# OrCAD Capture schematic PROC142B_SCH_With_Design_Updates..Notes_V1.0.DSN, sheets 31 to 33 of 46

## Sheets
31 31. JTAG BUFFER: size C; title: SOC JTAG INTERFACE AND JTAG BUFFERS
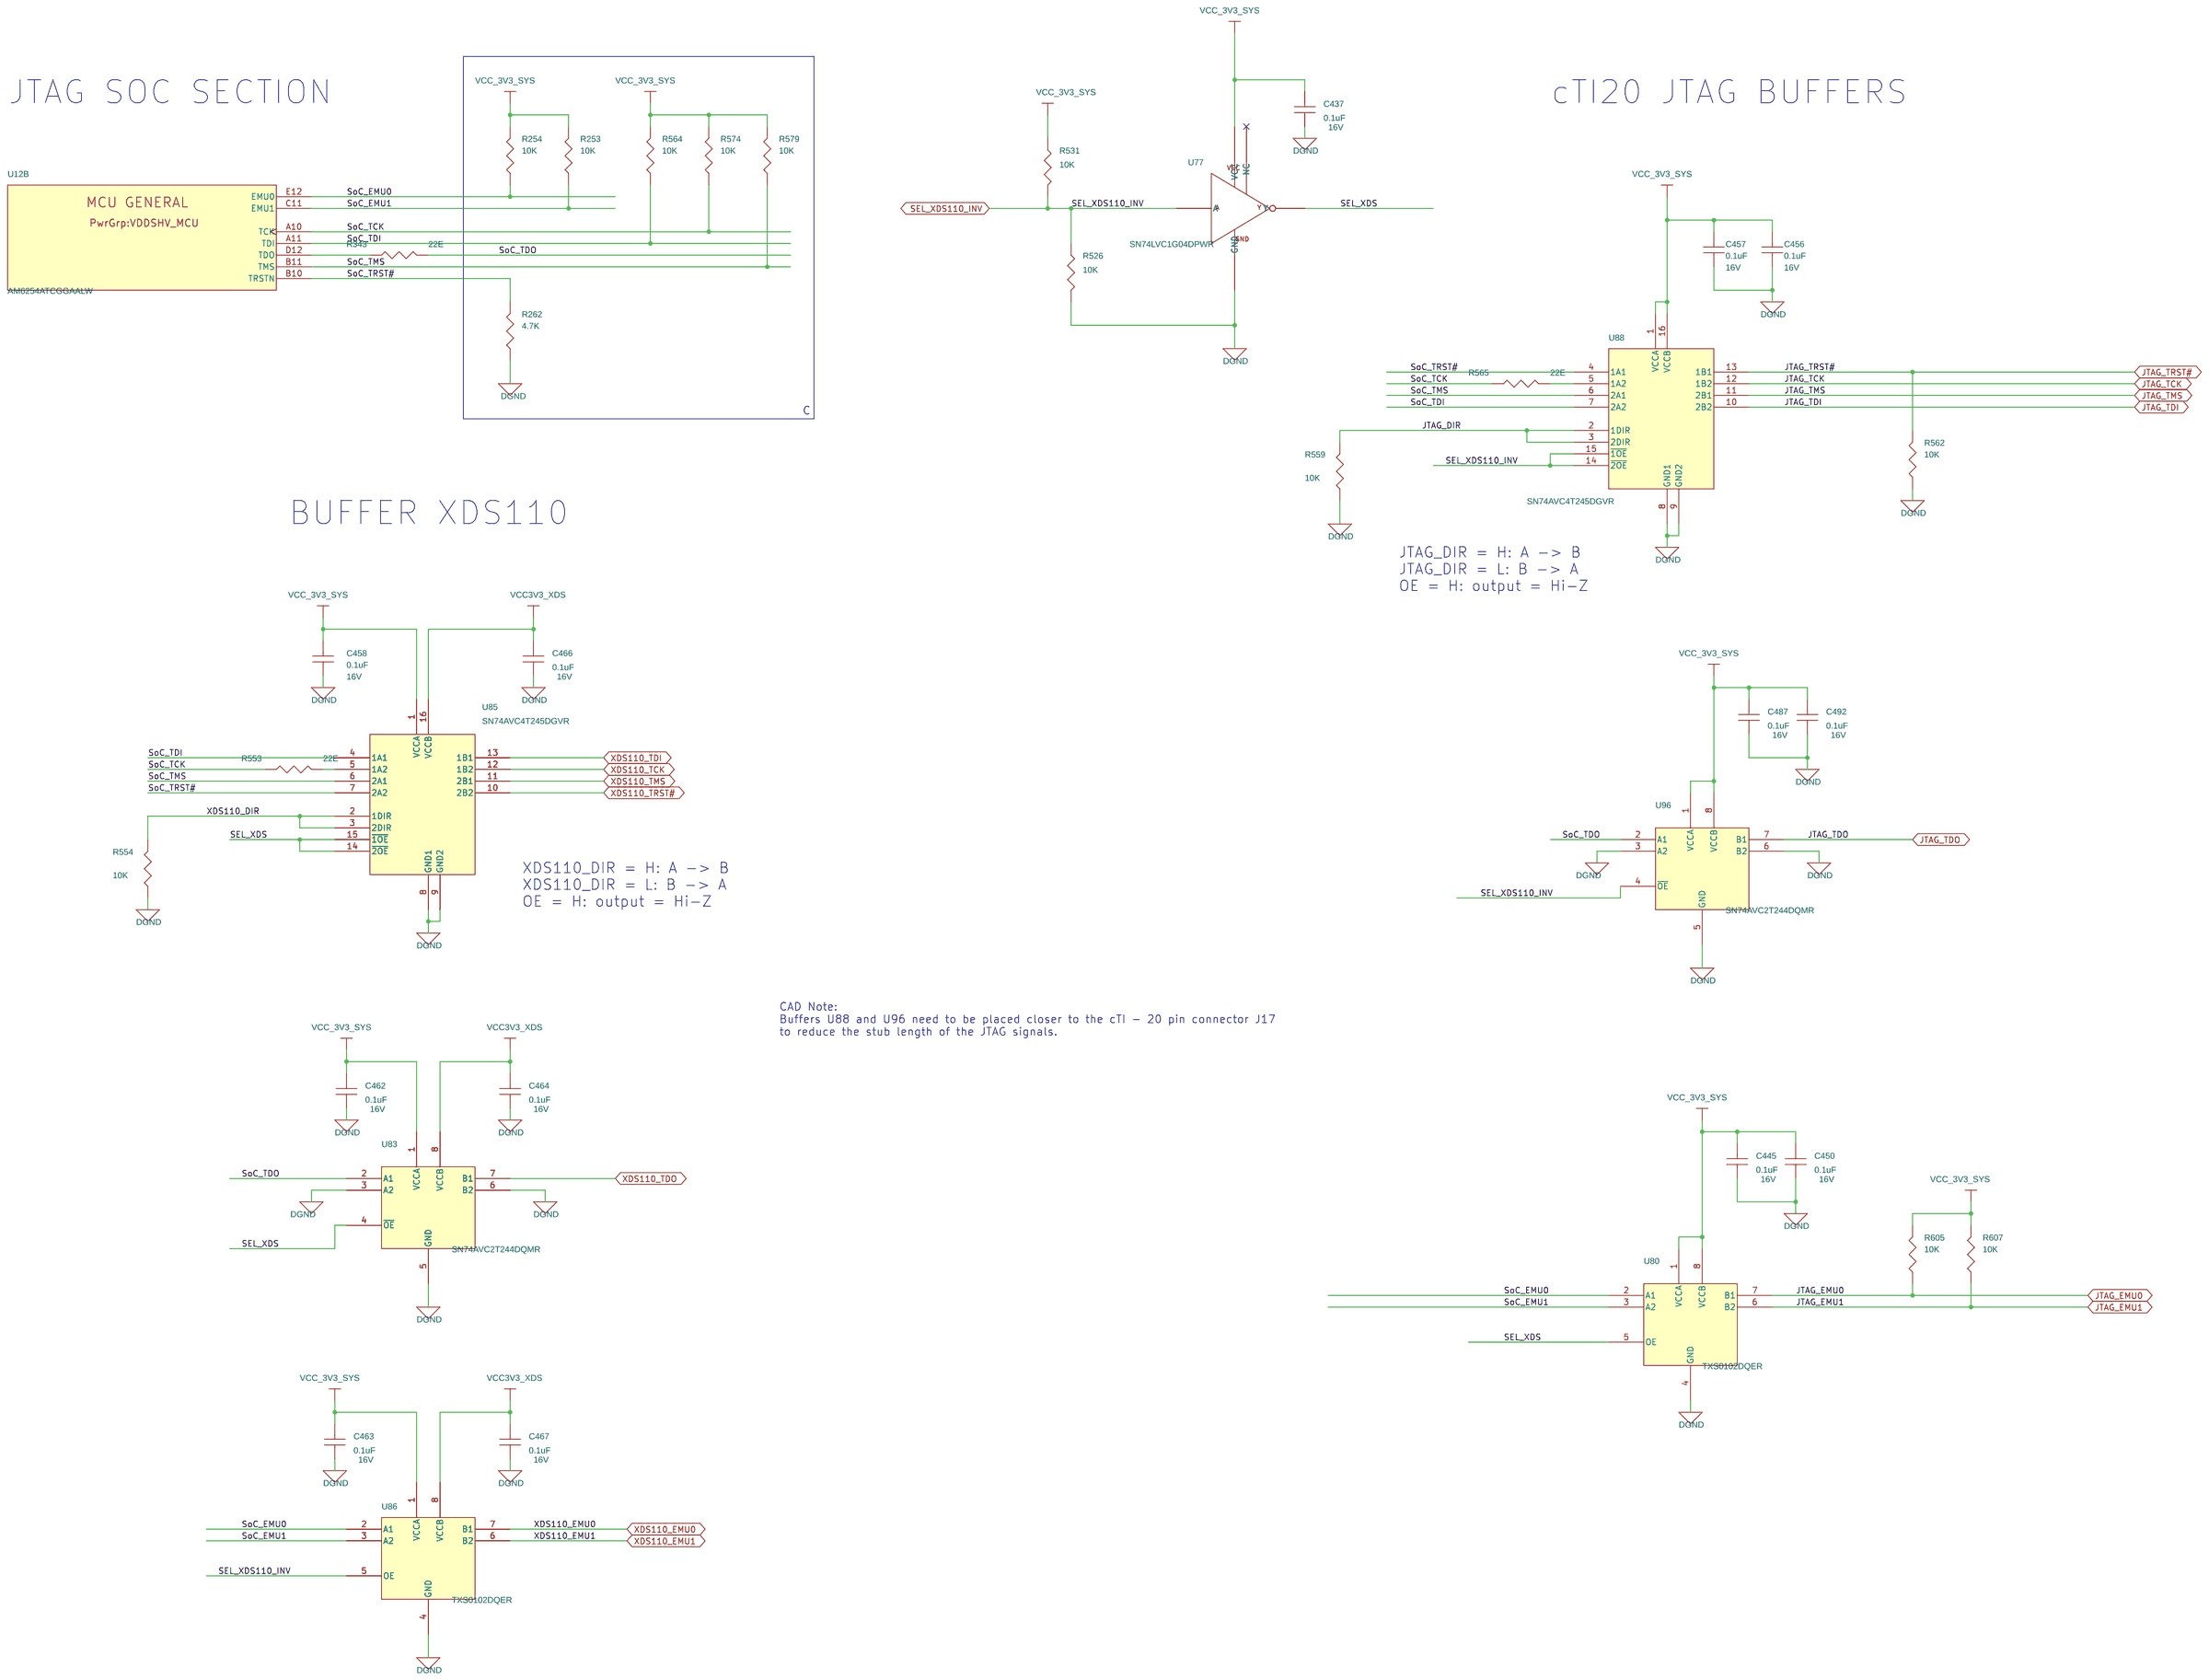
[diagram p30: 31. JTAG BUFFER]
32 32. JTAG 20 PIN cTI CONNECTOR: size C; title: JTAG 20 PIN cTI CONNECTOR AND BUFFERS
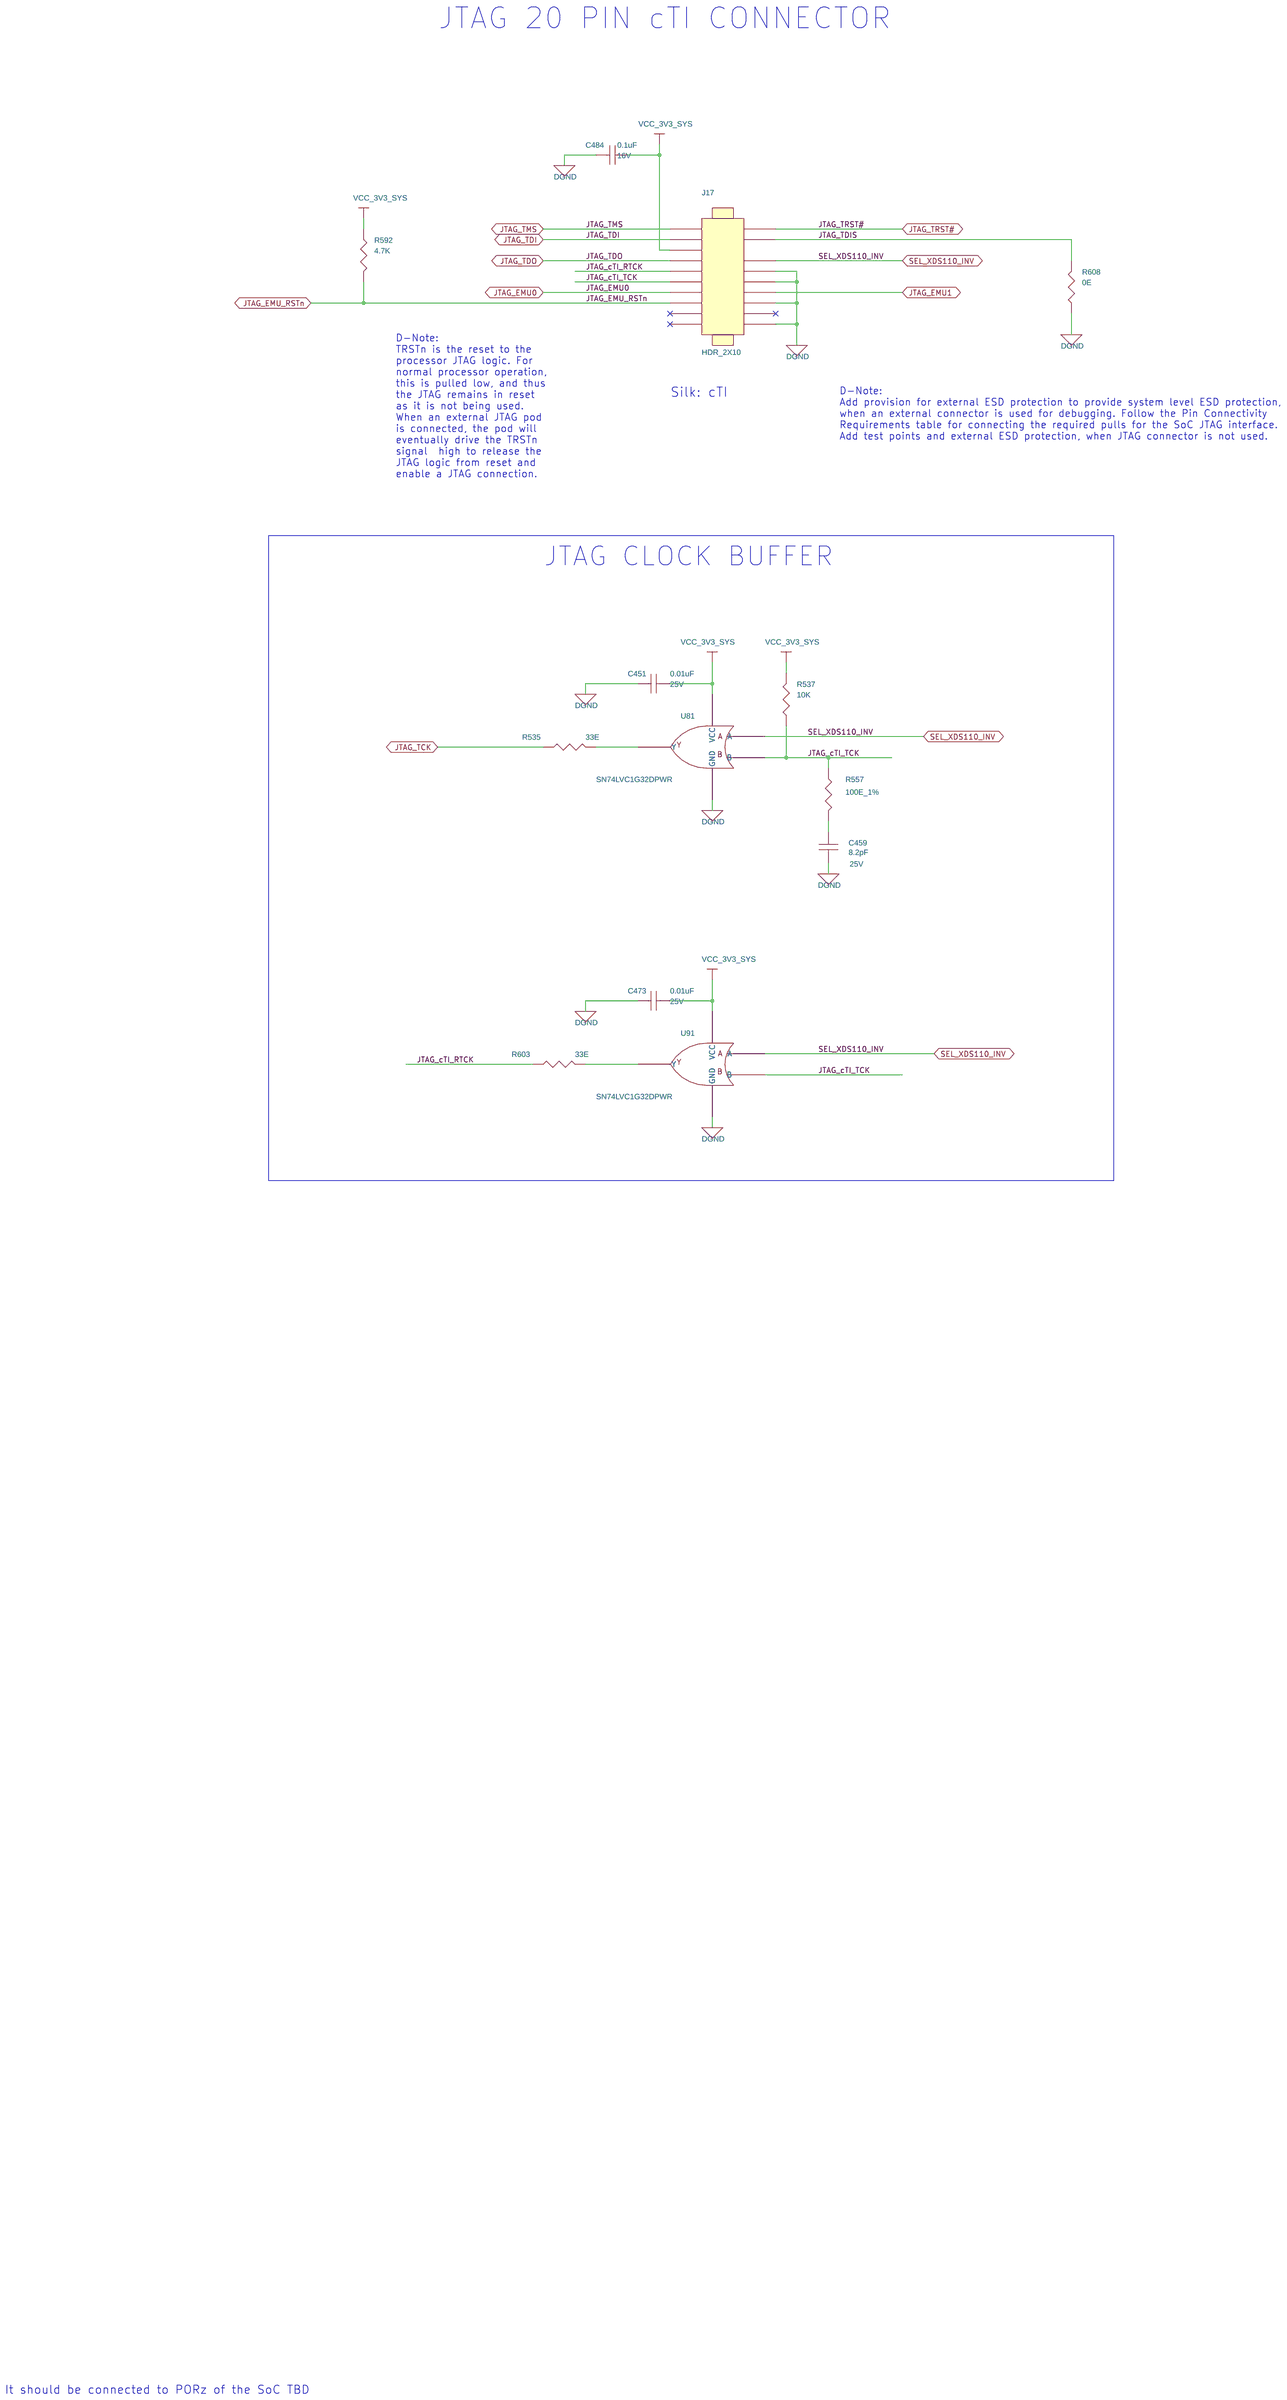
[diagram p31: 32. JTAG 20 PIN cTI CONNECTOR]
33 33. FT4232 UART TO USB BRIDGE: size C; title: FT4232 UART TO USB BRIDGE
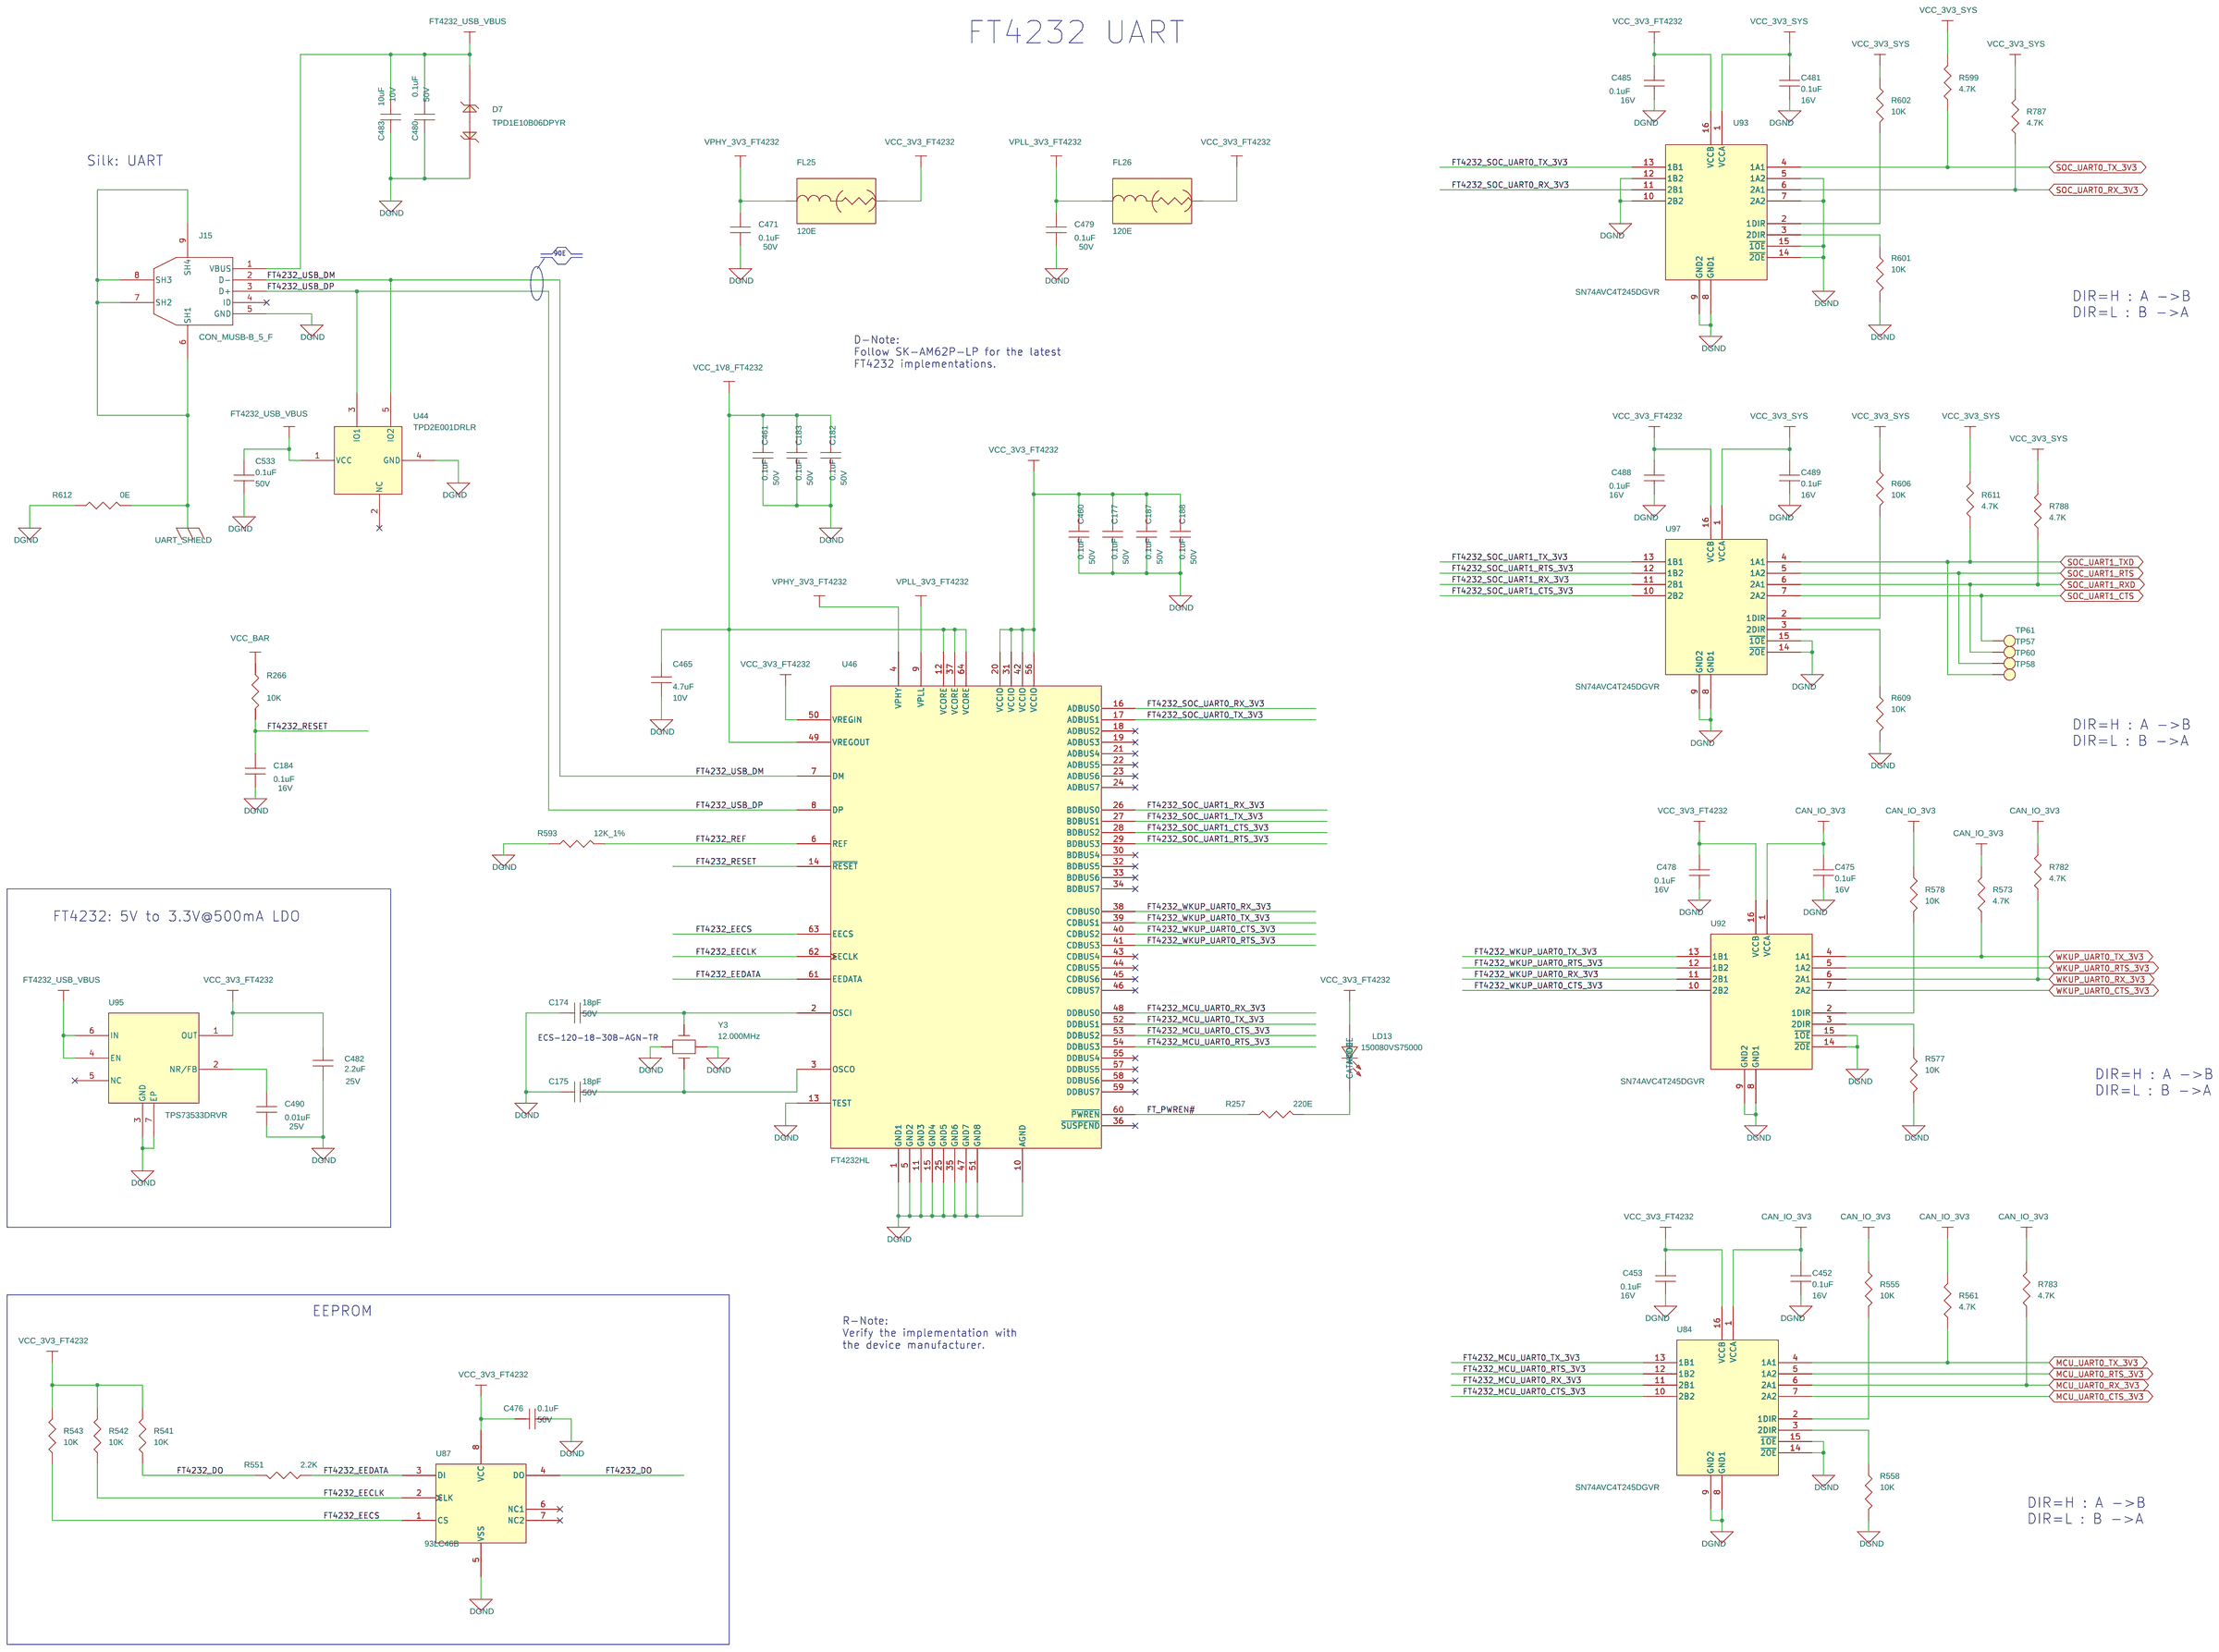
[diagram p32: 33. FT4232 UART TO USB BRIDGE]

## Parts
sheet 31. JTAG BUFFER
C437  0.1uF  [CAP0201_0-5]
C445  0.1uF  [CAP0201_0-5]
C450  0.1uF  [CAP0201_0-5]
C456  0.1uF  [CAP0201_0-5]
C457  0.1uF  [CAP0201_0-5]
C458  0.1uF  [CAP0201_0-5]
C462  0.1uF  [CAP0201_0-5]
C463  0.1uF  [CAP0201_0-5]
C464  0.1uF  [CAP0201_0-5]
C466  0.1uF  [CAP0201_0-5]
C467  0.1uF  [CAP0201_0-5]
C487  0.1uF  [CAP0201_0-5]
C492  0.1uF  [CAP0201_0-5]
R253  10K  [RES0201_0-5]
R254  10K  [RES0201_0-5]
R262  4.7K  [RES0201_0-5]
R343  22E  [RES0402_0-5]
R526  10K  [RES0201_0-5]
R531  10K  [RES0201_0-5]
R553  22E  [RES0402_0-5]
R554  10K  [RES0201_0-5]
R559  10K  [RES0201_0-5]
R562  10K  [RES0201_0-5]
R564  10K  [RES0201_0-5]
R565  22E  [RES0402_0-5]
R574  10K  [RES0201_0-5]
R579  10K  [RES0201_0-5]
R605  10K  [RES0201_0-5]
R607  10K  [RES0201_0-5]
U77  SN74LVC1G04DPWR  [X2SON5_TLV7021_30X30_0-4]
U80  TXS0102DQER  [X2SON8_TXS0102_40X60_0-4]
U83  SN74AVC2T244DQMR  [X2SON8_15-74_70X50]
U85  SN74AVC4T245DGVR  [TVSOP16_15-74_150X180]
U86  TXS0102DQER  [X2SON8_TXS0102_40X60_0-4]
U88  SN74AVC4T245DGVR  [TVSOP16_15-74_150X180]
U96  SN74AVC2T244DQMR  [X2SON8_15-74_70X50]
sheet 32. JTAG 20 PIN cTI CONNECTOR
C451  0.01uF  [CAP0201_0-5]
C459  8.2pF  [CAP0201_0-5]
C473  0.01uF  [CAP0201_0-5]
C484  0.1uF  [CAP0201_0-5]
J17  HDR_2X10  [HDR_2X10_FTR-110-51-D-06_S_S_8-7]
R535  33E  [RES0201_0-5]
R537  10K  [RES0201_0-5]
R557  100E_1%  [RES0402_0-5]
R592  4.7K  [RES0201_0-5]
R603  33E  [RES0201_0-5]
R608  0E  [RES0201_0-5]
U81  SN74LVC1G32DPWR  [X2SON5_TLV7021_30X30_0-4]
U91  SN74LVC1G32DPWR  [X2SON5_TLV7021_30X30_0-4]
sheet 33. FT4232 UART TO USB BRIDGE
C174  18pF  [CAP0402_0-75]
C175  18pF  [CAP0402_0-75]
C177  0.1uF  [CAP0402_0-75]
C182  0.1uF  [CAP0402_0-75]
C183  0.1uF  [CAP0402_0-75]
C184  0.1uF  [CAP0201_0-5]
C187  0.1uF  [CAP0402_0-75]
C188  0.1uF  [CAP0402_0-75]
C452  0.1uF  [CAP0201_0-5]
C453  0.1uF  [CAP0201_0-5]
C460  0.1uF  [CAP0402_0-75]
C461  0.1uF  [CAP0402_0-75]
C465  4.7uF  [CAP0402_0-75]
C471  0.1uF  [CAP0402_0-75]
C475  0.1uF  [CAP0201_0-5]
C476  0.1uF  [CAP0402_0-75]
C478  0.1uF  [CAP0201_0-5]
C479  0.1uF  [CAP0402_0-75]
C480  0.1uF  [CAP0402_0-75]
C481  0.1uF  [CAP0201_0-5]
C482  2.2uF  [CAP0402_0-75]
C483  10uF  [CAP0402_0-75]
C485  0.1uF  [CAP0201_0-5]
C488  0.1uF  [CAP0201_0-5]
C489  0.1uF  [CAP0201_0-5]
C490  0.01uF  [CAP0201_0-5]
C533  0.1uF  [CAP0402_0-75]
D7  TPD1E10B06DPYR  [DIO_DFN0402_0-5]
FL25  120E  [EMIFIL_BLM15A_0402_0-6]
FL26  120E  [EMIFIL_BLM15A_0402_0-6]
J15  CON_MUSB-B_5_F  [CON_MUSBB5_629105150521_S_R_S_2-7]
LD13  150080VS75000  [LED_150080VS75000_80X50_SMD_0-8]
R257  220E  [RES0402_0-5]
R266  10K  [RES0402_0-5]
R541  10K  [RES0201_0-5]
R542  10K  [RES0201_0-5]
R543  10K  [RES0201_0-5]
R551  2.2K  [RES0402_0-5]
R555  10K  [RES0201_0-5]
R558  10K  [RES0201_0-5]
R561  4.7K  [RES0201_0-5]
R573  4.7K  [RES0201_0-5]
R577  10K  [RES0201_0-5]
R578  10K  [RES0201_0-5]
R593  12K_1%  [RES0402_0-5]
R599  4.7K  [RES0201_0-5]
R601  10K  [RES0201_0-5]
R602  10K  [RES0201_0-5]
R606  10K  [RES0201_0-5]
R609  10K  [RES0201_0-5]
R611  4.7K  [RES0201_0-5]
R612  0E  [RES0805_0-75]
R782  4.7K  [RES0201_0-5]
R783  4.7K  [RES0201_0-5]
R787  4.7K  [RES0201_0-5]
R788  4.7K  [RES0201_0-5]
TP57  THRU HOLE  [TP_36X22]
TP58  THRU HOLE  [TP_36X22]
TP60  TP20_SMD  [TP20_SMD]
TP61  TP20_SMD  [TP20_SMD]
U44  TPD2E001DRLR  [SOT553-5_0-6]
U46  FT4232HL  [LQFP64_19-68_390X390_1-6]
U84  SN74AVC4T245DGVR  [TVSOP16_15-74_150X180]
U87  93LC46B  [MSOP8_25-59_125X125_1-1]
U92  SN74AVC4T245DGVR  [TVSOP16_15-74_150X180]
U93  SN74AVC4T245DGVR  [TVSOP16_15-74_150X180]
U95  TPS73533DRVR  [SON6_25-59_85X85]
U97  SN74AVC4T245DGVR  [TVSOP16_15-74_150X180]
Y3  12.000MHz  [XTAL4_ECX-53BQ_200X130_SMD_0-9]
sheet 43. HDMI INTERFACE
U12  AM6254ATCGGAALW  [BGA425_19-68_510X510_0-7]  (sections A,B,C,D,E,F,G,H,I,J,K,L,M,N,O,P,Q,R)

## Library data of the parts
C184 C437 C445 C450 C452 C453 C456-C458 C462-C464 C466 C467 C475 C478 C481 C484 C485 C487-C489 C492 = CAP: CAP CERAMIC 0.1uF 16V 10% X5R 0201; Alt_Mfr_name: YAGEO AMERICA; Alt_Mfr_part_number: CC0402KRX5R8BB104; Chkd/date: MANIRAJA/230118; Crtd /date: MANIRAJA/230118; Custom_Duty: 15%; Customs_HS_Code: 85322990; Distributor_name: DIGIKEY; Distributor_part_number: 490-14305-1-ND; Footprint Path: Y:\MIS_DATABASE\Library\ALTIUM_TOOL\PCB_FOOTPRINTS\Altium_Footprint_Lib.PcbLib; Height: 0.33MM; Library Path: Y:\MIS_DATABASE\Library\ALTIUM_TOOL\SCHEMATICS_PARTS\MS_DISCRETE_Library.schlib; Mfr_name: MURATA; Mfr_part_number: GRM033R61C104KE14D; Mistral Part No: 120009030072-R; Package: 0201; Part_type: CAPACITORS\CERAMIC; Project: TI_MAXIE_CPB; RoHS: RoHS; Temperature: -55°C+85°C; Tolerance: 10%; Voltage: 16V; Wattage: NA; Weight: 0.33mg; Datasheet: Y:\MIS_DATABASE\DATASHEETS\CAPACITORS\GRM033R61C104KE14.PDF
R253 R254 R526 R531 R537 R541-R543 R554 R555 R558 R559 R562 R564 R574 R577-R579 R601 R602 R605-R607 R609 = RESISTOR: RES 10K 1/20W 5% 0201; Chkd/date: MANIRAJA/050517; Crtd /date: MANIRAJA/050517; Custom_Duty: 15%; Customs_HS_Code: 85332119; Distributor_name: DIGIKEY; Distributor_part_number: 311-10KNCT-ND; Footprint Path: Y:\MIS_DATABASE\Library\ALTIUM_TOOL\PCB_FOOTPRINTS\Altium_Footprint_Lib.PcbLib; Height: 0.26MM; Library Path: Y:\MIS_DATABASE\Library\ALTIUM_TOOL\SCHEMATICS_PARTS\MS_DISCRETE_Library.schlib; Mfr_name: YAGEO AMERICA; Mfr_part_number: RC0201JR-0710KL; Mistral Part No: 110010070051-R; Package: 0201; Part_type: RESISTORS\FIXED; Project: GOLDEN-I LITE; RoHS: RoHS; Temperature: -55°C+125°C; Tolerance: 5%; Voltage: NA; Wattage: 1/20W; Weight: 0.17mg; Datasheet: Y:\MIS_DATABASE\DATASHEETS\RESISTORS\RCXXXXL-SER_MAR18.PDF
R262 R561 R573 R592 R599 R611 R782 R783 R787 R788 = RESISTOR: RES 4.7K 1/20W 5% 0201; Chkd/date: MANIRAJA/200921; Crtd /date: ALVY/200921; Custom_Duty: 15%; Customs_HS_Code: 85332119; Distributor_name: DIGIKEY; Distributor_part_number: 311-4.7KNCT-ND; Footprint Path: Y:\MIS_DATABASE\Library\ALTIUM_TOOL\PCB_FOOTPRINTS\Altium_Footprint_Lib.PcbLib; Height: 0.26MM; Library Path: Y:\MIS_DATABASE\Library\ALTIUM_TOOL\SCHEMATICS_PARTS\MS_DISCRETE_Library.schlib; Mfr_name: YAGEO AMERICA; Mfr_part_number: RC0201JR-074K7L; Mistral Part No: 110021090007-R; Package: 0201; Part_type: RESISTORS\FIXED; Project: TI_AM62x SKEVM_BRD; RoHS: RoHS; Temperature: -55°C+125°C; Tolerance: 5%; Voltage: NA; Wattage: 1/20W; Weight: 0.17mg; Datasheet: Y:\MIS_DATABASE\DATASHEETS\RESISTORS\RCXXXXL-SER_MAR18.PDF
R343 R553 R565 = RESISTOR: RES 22E 1/16W 5% 0402; Chkd/date: ALVY/210122; Crtd /date: TAMILARASU/210122; Custom_Duty: 15%; Customs_HS_Code: 85332119; Distributor_name: DIGIKEY; Distributor_part_number: 311-22JRCT-ND; Footprint Path: Y:\MIS_DATABASE\Library\ALTIUM_TOOL\PCB_FOOTPRINTS\Altium_Footprint_Lib.PcbLib; Height: 0.40MM; Library Path: Y:\MIS_DATABASE\Library\ALTIUM_TOOL\SCHEMATICS_PARTS\MS_DISCRETE_Library.schlib; Manufacturer: YAGEO; Mfr_name: YAGEO AMERICA; Mfr_part_number: RC0402JR-0722RL; Mistral Part No: 110022010018-R; Package: 0402; Part_type: RESISTORS\FIXED; Project: DLRL DIGITAL RECEIVER_BRD; RoHS: RoHS; Temperature: -55°C+155°C; Tolerance: 5%; Voltage: NA; Wattage: 1/16W; Weight: 0.65mg; Datasheet: Y:\MIS_DATABASE\DATASHEETS\RESISTORS\RCXXXXP-SER_SEP18.PDF
U77 = SN74LVC1G04DCKR_SC70-5: IC SINGLE INVERTER GATE X2SON5; Chkd/date: MANIRAJA/141020; Crtd /date: ALVY/131020; Custom_Duty: 15%; Customs_HS_Code: 85423100; Distributor_name: DIGIKEY; Distributor_part_number: 296-37758-1-ND; Footprint Path: Y:\MIS_DATABASE\Library\ALTIUM_TOOL\PCB_FOOTPRINTS\Altium_Footprint_Lib.PcbLib; Height: 0.40MM; Library Path: Y:\MIS_DATABASE\Library\ALTIUM_TOOL\SCHEMATICS_PARTS\MS_GATE_Library.schlib; Mfr_name: TEXAS INSTRUMENTS; Mistral Part No: 141020100010-R; Package: X2SON5; Part_type: ICS\DIGITAL\GATES; Project: AM64X_SKEVM; RoHS: RoHS; Temperature: -40°C+125°C; Tolerance: NA; Voltage: NA; Wattage: NA; Weight: 0.6mg; Datasheet: Y:\MIS_DATABASE\DATASHEETS\ICS\DIGITAL\GATES\SN74LVC1G04XX.PDF
U80 U86 = TXS0102DQX_SON8: IC 2-BIT BI-DIR VOLTAGE-LEVEL TRANSLATOR FOR OPEN-DRAIN AND PUSH-PULL X2SON8; Chkd/date: MANIRAJA/010719; Crtd /date: CHAITHANYA230512; Custom_Duty: 15%; Customs_HS_Code: 85423100; Distributor_name: DIGIKEY; Distributor_part_number: 296-28368-1-ND; Footprint Path: Y:\MIS_DATABASE\Library\ALTIUM_TOOL\PCB_FOOTPRINTS\Altium_Footprint_Lib.PcbLib; Height: 0.40MM; Library Path: Y:\MIS_DATABASE\Library\ALTIUM_TOOL\SCHEMATICS_PARTS\MS_MISCINTERFACE_Library.schlib; Mfr_name: TEXAS INSTRUMENTS; Mistral Part No: 141012050010-R; Package: X2SON8; Part_type: ICS\INTERFACE\LEVEL TRANSLATOR; Project: GEN_3-8_DB; RoHS: RoHS; Temperature: -40°C+85°C; Tolerance: NA; Voltage: NA; Wattage: NA; Weight: 1.2mg; Datasheet: Y:\MIS_DATABASE\DATASHEETS\ICS\INTERFACE\TXS0102-SER.PDF
U83 U96 = SN74AVC2T244DQMR_X2SON8: IC 2-BIT UNDIRECTIONAL VOLTAGE-LEVEL TRANSLATOR X2SON8; Chkd/date: VASANTHA/060516; Crtd /date: VASANTHA/030316; Customs_HS_Code: 15%; Distributor_name: DIGIKEY; Distributor_part_number: 296-29674-1-ND; Height: 0.40MM; Mfr_name: TEXAS INSTRUMENTS; Mistral Part No: 141016030002-R; Package: X2SON8; Part_type: ICS\INTERFACE\LEVEL TRANSLATOR; Pb-Free: 85423100; Project: OCTASIC_3600; RoHS: RoHS; Temperature: -40°C+85°C; Tolerance: NA; Voltage: NA; Wattage: NA; Weight: NA; Datasheet: Y:\MIS_DATABASE\DATASHEETS\ICS\INTERFACE\SN74AVC2T244.PDF
U84 U85 U88 U92 U93 U97 = SN74AVC4T245DGVR_TVSOP16: IC 4-BIT DUAL SUPPLY BUS TRANSCEIVER TVSOP16; Chkd/date: SUHAS/251010; Crtd /date: MAZHAR/201109; Custom_Duty: 15%; Customs_HS_Code: 85423100; Distributor_name: DIGIKEY; Distributor_part_number: 296-18054-1-ND; Height: 1.20MM; Mfr_name: TEXAS INSTRUMENTS; Mistral Part No: 141009110005-P; Package: TVSOP16; Part_type: ICS\DIGITAL\COMBINATIONAL; Project: GOLDEN-I; RoHS: Sb/ Br FREE; Temperature: -40°C+85°C; Datasheet: Y:\MIS_DATABASE\DATASHEETS\ICS\DIGITAL\BUSTRANSCEIVER\SN74AVC4T245.PDF
C451 C473 C490 = CAP: CAP CERAMIC 0.01uF 25V 10% X5R 0201; Chkd/date: MANIRAJA/230118; Crtd /date: MANIRAJA/230118; Custom_Duty: 15%; Customs_HS_Code: 85322990; Distributor_name: DIGIKEY; Distributor_part_number: GRM033R61E103KA12J-ND; Footprint Path: Y:\MIS_DATABASE\Library\ALTIUM_TOOL\PCB_FOOTPRINTS\Altium_Footprint_Lib.PcbLib; Height: 0.33MM; Library Path: Y:\MIS_DATABASE\Library\ALTIUM_TOOL\SCHEMATICS_PARTS\MS_DISCRETE_Library.schlib; Mfr_name: MURATA; Mfr_part_number: GRM033R61E103KA12J; Mistral Part No: 120018010007-R; Package: 0201; Part_type: CAPACITORS\CERAMIC; Project: TI_MAXIE_CPB; RoHS: RoHS; Temperature: -55°C+85°C; Tolerance: 10%; Voltage: 25V; Wattage: NA; Weight: 0.33mg; Datasheet: Y:\MIS_DATABASE\DATASHEETS\CAPACITORS\GRM033R61E103KA12.PDF
C459 = CAP: CAP CERAMIC 8.2pF 25V 0.5pF C0G(NP0) 0201; Chkd/date: MANIRAJA/121020; Crtd /date: ALVY/091020; Custom_Duty: 15%; Customs_HS_Code: 85322990; Distributor_name: DIGIKEY; Distributor_part_number: 490-3140-1-ND; Footprint Path: Y:\MIS_DATABASE\Library\ALTIUM_TOOL\PCB_FOOTPRINTS\Altium_Footprint_Lib.PcbLib; Height: 0.33MM; Library Path: Y:\MIS_DATABASE\Library\ALTIUM_TOOL\SCHEMATICS_PARTS\MS_DISCRETE_Library.schlib; Mfr_name: MURATA; Mfr_part_number: GRM0335C1E8R2DA01D; Mistral Part No: 120020100018-R; Package: 0201; Part_type: CAPACITORS\CERAMIC; Project: AM64X_SKEVM; RoHS: RoHS; Temperature: -55°C+125°C; Tolerance: 0.5pF%; Voltage: 25V; Wattage: NA; Weight: 0.33mg; Datasheet: Y:\MIS_DATABASE\DATASHEETS\CAPACITORS\GRM0335C1E8R2DA01.PDF
J17 = HEADER_10X2_FTR-06: CON HDR 2X10 1.27MM PITCH ST SMD; Chkd/date: MANIRAJA/031218; Crtd /date: CHAITHANYA/050811; Custom_Duty: 24%; Customs_HS_Code: 85369090; Distributor_name: DIGIKEY; Distributor_part_number: SAM8792-ND; Footprint Path: Y:\MIS_DATABASE\Library\ALTIUM_TOOL\PCB_FOOTPRINTS\Altium_Footprint_Lib.PcbLib; Height: 8.67MM; Library Path: Y:\MIS_DATABASE\Library\ALTIUM_TOOL\SCHEMATICS_PARTS\MS_CONNECTOR_Library.schlib; Mfr_name: SAMTEC; Mfr_part_number: FTR-110-51-S-D-06; Mistral Part No: 150011090001-R; Package: SMD; Part_type: CONNECTOR\HEADERS; Project: GEMYC; RoHS: RoHS; Temperature: -55°C+125°C; Tolerance: NA; Voltage: NA; Wattage: NA; Weight: NA; Datasheet: Y:\MIS_DATABASE\DATASHEETS\CONNECTORS\FTR-D-SER.PDF
R535 R603 = RESISTOR: RES 33E 1/20W 5% 0201; Chkd/date: VASANTHA/061216; Crtd /date: MAZHAR/170505; Custom_Duty: 15%; Customs_HS_Code: 85332119; Distributor_name: DIGIKEY; Distributor_part_number: P33AGCT-ND; Footprint Path: Y:\MIS_DATABASE\Library\ALTIUM_TOOL\PCB_FOOTPRINTS\Altium_Footprint_Lib.PcbLib; Height: 0.26MM; Library Path: Y:\MIS_DATABASE\Library\ALTIUM_TOOL\SCHEMATICS_PARTS\MS_DISCRETE_Library.schlib; Mfr_name: PANASONIC-ECG; Mfr_part_number: ERJ-1GEJ330C; Mistral Part No: 110010070052-R; Package: 0201; Part_type: RESISTORS\FIXED; Project: G4SLIM; RoHS: RoHS; Temperature: -55°C+125°C; Tolerance: 5%; Voltage: NA; Wattage: 1/20W; Weight: 0.15mg; Datasheet: Y:\MIS_DATABASE\DATASHEETS\RESISTORS\PAN-ERJXGE-FEB06.PDF
R557 = RESISTOR: RES 100E 1/16W 1% 0402; Chkd/date: MANIRAJA/060318; Crtd /date: NAVEED/220714; Custom_Duty: 15%; Customs_HS_Code: 85332119; Distributor_name: DIGIKEY; Distributor_part_number: 311-100LRCT-ND; Footprint Path: Y:\MIS_DATABASE\Library\ALTIUM_TOOL\PCB_FOOTPRINTS\Altium_Footprint_Lib.PcbLib; Height: 0.40MM; Library Path: Y:\MIS_DATABASE\Library\ALTIUM_TOOL\SCHEMATICS_PARTS\MS_DISCRETE_Library.schlib; Mfr_name: YAGEO AMERICA; Mfr_part_number: RC0402FR-07100RL; Mistral Part No: 110014070015-R; Package: 0402; Part_type: RESISTORS\FIXED; Project: DLRU; RoHS: RoHS; Temperature: -55°C+155°C; Tolerance: 1%; Voltage: NA; Wattage: 1/16W; Weight: 0.65mg; Datasheet: Y:\MIS_DATABASE\DATASHEETS\RESISTORS\RCXXXXL-SER_MAR18.PDF
R608 = RESISTOR: RES 0E 1/20W 5% 0201; Chkd/date: NAVEED/301214; Crtd /date: MUDDU/120710; Custom_Duty: 15%; Customs_HS_Code: 85332119; Distributor_name: DIGIKEY; Distributor_part_number: 311-0.0NCT-ND; Footprint Path: Y:\MIS_DATABASE\Library\ALTIUM_TOOL\PCB_FOOTPRINTS\Altium_Footprint_Lib.PcbLib; Height: 0.26MM; Library Path: Y:\MIS_DATABASE\Library\ALTIUM_TOOL\SCHEMATICS_PARTS\MS_DISCRETE_Library.schlib; Mfr_name: YAGEO AMERICA; Mfr_part_number: RC0201JR-070RL; Mistral Part No: 110010070067-R; Package: 0201; Part_type: RESISTORS\FIXED; Project: PB_BUGBASE; RoHS: RoHS; Temperature: -55°C+125°C; Tolerance: 5%; Voltage: NA; Wattage: 1/20W; Weight: 0.17mg; Datasheet: Y:\MIS_DATABASE\DATASHEETS\RESISTORS\RCXXXXL-SER_MAR18.PDF
U81 U91 = SN74LVC1G32_X2SON5: IC SINGLE 2-INPUT POSITIVE-OR GATE X2SON5; Chkd/date: MANIRAJA/141020; Crtd /date: ALVY/131020; Custom_Duty: 15%; Customs_HS_Code: 85423100; Distributor_name: DIGIKEY; Distributor_part_number: 296-SN74LVC1G32DPWRCT-ND; Footprint Path: Y:\MIS_DATABASE\Library\ALTIUM_TOOL\PCB_FOOTPRINTS\Altium_Footprint_Lib.PcbLib; Height: 0.40MM; Library Path: Y:\MIS_DATABASE\Library\ALTIUM_TOOL\SCHEMATICS_PARTS\MS_GATE_Library.schlib; Mfr_name: TEXAS INSTRUMENTS; Mistral Part No: 141020100011-R; Package: X2SON5; Part_type: ICS\DIGITAL\GATES; Project: AM64X_SKEVM; RoHS: RoHS; Temperature: -40°C+125°C; Tolerance: NA; Voltage: NA; Wattage: NA; Weight: 0.6mg; Datasheet: Y:\MIS_DATABASE\DATASHEETS\ICS\DIGITAL\GATES\SN74LVC1G32XX.PDF
C174 C175 = CAP: CAP CERAMIC 18pF 50V 5% HI-Q C0G(NP0) 0402; Chkd/date: VASANTHA/030315; Crtd /date: NAVEED/271014; Custom_Duty: 15%; Customs_HS_Code: 85322990; Distributor_name: DIGIKEY; Distributor_part_number: 490-3119-1-ND; Footprint Path: Y:\MIS_DATABASE\Library\ALTIUM_TOOL\PCB_FOOTPRINTS\Altium_Footprint_Lib.PcbLib; Height: 0.55MM; Library Path: Y:\MIS_DATABASE\Library\ALTIUM_TOOL\SCHEMATICS_PARTS\MS_DISCRETE_Library.schlib; Mfr_name: MURATA; Mfr_part_number: GJM1555C1H180JB01D; Mistral Part No: 120014100019-R; Package: 0402; Part_type: CAPACITORS\CERAMIC; Project: DC_MIST_RDC; RoHS: RoHS; Temperature: -55°C+125°C; Tolerance: 5%; Voltage: 50V; Wattage: NA; Weight: 6mg; Datasheet: Y:\MIS_DATABASE\DATASHEETS\CAPACITORS\MURATA-GXX-SER_NOV17.PDF
C177 C182 C183 C187 C188 C460 C461 C471 C476 C479 C480 C533 = CAP: CAP CERAMIC 0.1uF 50V 10% X7R 0402; Alt_Mfr_name: YAGEO AMERICA; Alt_Mfr_part_number: CC0402KRX5R8BB104; Chkd/date: MANIRAJA/261020; Crtd /date: ALVY/211020; Custom_Duty: 15%; Customs_HS_Code: 85322990; Distributor_name: DIGIKEY; Distributor_part_number: 490-10700-1-ND; Footprint Path: Y:\MIS_DATABASE\Library\ALTIUM_TOOL\PCB_FOOTPRINTS\Altium_Footprint_Lib.PcbLib; Height: 0.55MM; Library Path: Y:\MIS_DATABASE\Library\ALTIUM_TOOL\SCHEMATICS_PARTS\MS_DISCRETE_Library.schlib; Mfr_name: MURATA; Mfr_part_number: GRM155R71H104KE14D; Mistral Part No: 120011100014-R; Package: 0402; Part_type: CAPACITORS\CERAMIC; Project: J7_CP; RoHS: RoHS; Temperature: -55°C+125°C; Tolerance: 10%; Voltage: 50V; Wattage: NA; Weight: 3.1mg; Datasheet: Y:\MIS_DATABASE\DATASHEETS\CAPACITORS\GRM155R71H104KE14.PDF
C465 = CAP: CAP CERAMIC 4.7uF 10V 20% X5R 0402; Chkd/date: MANIRAJA/110718; Crtd /date: ALVY/110718; Custom_Duty: 15%; Customs_HS_Code: 85322990; Distributor_name: DIGIKEY; Distributor_part_number: 490-14306-1-ND; Footprint Path: Y:\MIS_DATABASE\Library\ALTIUM_TOOL\PCB_FOOTPRINTS\Altium_Footprint_Lib.PcbLib; Height: 0.65MM; Library Path: Y:\MIS_DATABASE\Library\ALTIUM_TOOL\SCHEMATICS_PARTS\MS_DISCRETE_Library.schlib; Mfr_name: MURATA; Mfr_part_number: GRM155R61A475MEAAD; Mistral Part No: 120012060002-R; Package: 0402; Part_type: CAPACITORS\CERAMIC; Project: TI_J7SVB_PCIE_ADD-ON-CARD; RoHS: RoHS; Temperature: -55°C+85°C; Tolerance: 20%; Voltage: 10V; Wattage: NA; Weight: 14mg; Datasheet: Y:\MIS_DATABASE\DATASHEETS\CAPACITORS\GRM155R61A475MEAAD.PDF
C482 = CAP: CAP CERAMIC 2.2uF 25V 10% X5R 0402; Chkd/date: ALVY/010721; Crtd /date: MANIRAJA/010721; Custom_Duty: 15%; Customs_HS_Code: 85322990; Distributor_name: DIGIKEY; Distributor_part_number: 490-12703-1-ND; Footprint Path: Y:\MIS_DATABASE\Library\ALTIUM_TOOL\PCB_FOOTPRINTS\Altium_Footprint_Lib.PcbLib; Height: 0.70MM; Library Path: Y:\MIS_DATABASE\Library\ALTIUM_TOOL\SCHEMATICS_PARTS\MS_DISCRETE_Library.schlib; Mfr_name: MURATA; Mfr_part_number: GRM155R61E225KE11D; Mistral Part No: 120015120001-R; Package: 0402; Part_type: CAPACITORS\CERAMIC; Project: TI_AM263X_CC; RoHS: RoHS; Temperature: -55°C+85°C; Tolerance: 10%; Voltage: 25V; Wattage: NA; Weight: 1.5mg; Datasheet: Y:\MIS_DATABASE\DATASHEETS\CAPACITORS\GRM155R61E225KE11.PDF
C483 = CAP: CAP CERAMIC 10uF 10V 20% X5R 0402; Chkd/date: MANIRAJA/300520; Crtd /date: ALVY/260520; Custom_Duty: 15%; Customs_HS_Code: 85322990; Distributor_name: DIGIKEY; Distributor_part_number: 490-GRM155R61A106ME11DTR-ND; Footprint Path: Y:\MIS_DATABASE\Library\ALTIUM_TOOL\PCB_FOOTPRINTS\Altium_Footprint_Lib.PcbLib; Height: 0.55MM; Library Path: Y:\MIS_DATABASE\Library\ALTIUM_TOOL\SCHEMATICS_PARTS\MS_DISCRETE_Library.schlib; Mfr_name: MURATA; Mfr_part_number: GRM155R61A106ME11D; Mistral Part No: 120013110019-R; Package: 0402; Part_type: CAPACITORS\CERAMIC; Project: QCS610_NANOSOM; RoHS: RoHS; Temperature: -55°C+85°C; Tolerance: 20%; Voltage: 10V; Wattage: NA; Weight: 3.1mg; Datasheet: Y:\MIS_DATABASE\DATASHEETS\CAPACITORS\MURATA-GXX-SER_NOV17.PDF
D7 = DIODE_SOD323: DIODE 1CH ESD PROTECTION X1SON2; Chkd/date: MANIRAJA/040420; Crtd /date: VASANTHA/181114; Custom_Duty: 15%; Customs_HS_Code: 85423100; Distributor_name: DIGIKEY; Distributor_part_number: 296-30406-1-ND; Footprint Path: Y:\MIS_DATABASE\Library\ALTIUM_TOOL\PCB_FOOTPRINTS\Altium_Footprint_Lib.PcbLib; Height: 0.45MM; Library Path: Y:\MIS_DATABASE\Library\ALTIUM_TOOL\SCHEMATICS_PARTS\MS_DISCRETE_Library.schlib; Mfr_name: TEXAS INSTRUMENTS; Mistral Part No: 130014110022-R; Package: X1SON2; Part_type: DIODE; Project: GALILEO_EVM; RoHS: RoHS; Temperature: -40°C+125°C; Tolerance: NA; Voltage: NA; Wattage: NA; Weight: 1mg; Datasheet: Y:\MIS_DATABASE\DATASHEETS\ICS\INTERFACE\TPD1E10B06-SER.PDF
FL25 FL26 = EMIFILTER_IND: IND FERRITE BEAD CHIP 120E 2A 0402; Chkd/date: NAVEED/241114; Crtd /date: USMAN/170613; Custom_Duty: 24%; Customs_HS_Code: 85369090; Distributor_name: DIGIKEY; Distributor_part_number: 490-9656-1-ND; Footprint Path: Y:\MIS_DATABASE\Library\ALTIUM_TOOL\PCB_FOOTPRINTS\Altium_Footprint_Lib.PcbLib; Height: 0.55MM; Library Path: Y:\MIS_DATABASE\Library\ALTIUM_TOOL\SCHEMATICS_PARTS\MS_FILTER_Library.schlib; Mfr_name: MURATA; Mfr_part_number: BLM15PX121SN1D; Mistral Part No: 130013060022-R; Package: 0402; Part_type: INDUCTOR; Project: GEN_3-8; RoHS: RoHS; Temperature: -55°C+125°C; Tolerance: 25%; Voltage: NA; Wattage: NA; Weight: 1mg; Datasheet: Y:\MIS_DATABASE\DATASHEETS\DISCRETES\INDUCTORS\BLM15-SN1-SER.PDF
J15 = CON_USB_MINI-B: CON MICRO USB TYPE B 5POS FEMALE RT SMD; Chkd/date: MANIRAJA/150519; Crtd /date: ALVY/150519; Custom_Duty: 24%; Customs_HS_Code: 85369090; Distributor_name: DIGIKEY; Distributor_part_number: 732-5960-1-ND; Footprint Path: Y:\MIS_DATABASE\Library\ALTIUM_TOOL\PCB_FOOTPRINTS\Altium_Footprint_Lib.PcbLib; Height: 2.66MM; Library Path: Y:\MIS_DATABASE\Library\ALTIUM_TOOL\SCHEMATICS_PARTS\MS_CONNECTOR_Library.schlib; Mfr_name: WURTH ELECTRONICS; Mfr_part_number: 629105150521; Mistral Part No: 150019050015-R; Package: SMD; Part_type: CONNECTOR\USB; Project: NEXTNAV_ALT-STATION_ATE_BRD; RoHS: RoHS; Temperature: -40°C+85°C; Tolerance: NA; Voltage: NA; Wattage: NA; Weight: 360mg; Datasheet: Y:\MIS_DATABASE\DATASHEETS\CONNECTORS\629105150521.PDF
LD13 = DIODE_LED: DIODE LED BRIGHT GREEN SMD; Chkd/date: MANIRAJA/180820; Crtd /date: ALVY/180820; Custom_Duty: 24%; Customs_HS_Code: 85439000; Distributor_name: DIGIKEY; Distributor_part_number: 732-4986-1-ND; Footprint Path: Y:\MIS_DATABASE\Library\ALTIUM_TOOL\PCB_FOOTPRINTS\Altium_Footprint_Lib.PcbLib; Height: 0.80MM; Library Path: Y:\MIS_DATABASE\Library\ALTIUM_TOOL\SCHEMATICS_PARTS\MS_OPTO_Library.schlib; Mfr_name: WURTH ELECTRONICS; Mistral Part No: 130020080012-R; Package: SMD; Part_type: OPTO\LED; Project: AM64x_EVM_BRD; RoHS: RoHS; Temperature: -40°C+85°C; Tolerance: NA; Voltage: NA; Wattage: NA; Weight: 10mg; Datasheet: Y:\MIS_DATABASE\DATASHEETS\DISCRETES\LEDS\150080VS75000.PDF
R257 = RESISTOR: RES 220E 1/10W 5% 0402; Chkd/date: VASANTHA/291216; Crtd /date: GEETHA/260406; Custom_Duty: 15%; Customs_HS_Code: 85332119; Distributor_name: DIGIKEY; Distributor_part_number: P220JCT-ND; Footprint Path: Y:\MIS_DATABASE\Library\ALTIUM_TOOL\PCB_FOOTPRINTS\Altium_Footprint_Lib.PcbLib; Height: 0.40MM; Library Path: Y:\MIS_DATABASE\Library\ALTIUM_TOOL\SCHEMATICS_PARTS\MS_DISCRETE_Library.schlib; Mfr_name: PANASONIC-ECG; Mfr_part_number: ERJ-2GEJ221X; Mistral Part No: 110009030506-R; Package: 0402; Part_type: RESISTORS\FIXED; Project: RED EYE; RoHS: RoHS; Temperature: -55°C+155°C; Tolerance: 5%; Voltage: NA; Wattage: 1/10W; Weight: 0.8mg; Datasheet: Y:\MIS_DATABASE\DATASHEETS\RESISTORS\PAN-ERJSER_NOV17.PDF
R266 = RESISTOR: RES 10K 1/16W 5% 0402; Chkd/date: MANIRAJA/120219; Crtd /date: MANIRAJA/120219; Custom_Duty: 15%; Customs_HS_Code: 85332119; Distributor_name: DIGIKEY; Distributor_part_number: 541-10KJCT-ND; Footprint Path: Y:\MIS_DATABASE\Library\ALTIUM_TOOL\PCB_FOOTPRINTS\Altium_Footprint_Lib.PcbLib; Height: 0.40MM; Library Path: Y:\MIS_DATABASE\Library\ALTIUM_TOOL\SCHEMATICS_PARTS\MS_DISCRETE_Library.schlib; Mfr_name: VISHAY; Mfr_part_number: CRCW040210K0JNED; Mistral Part No: 110011060021-R; Package: 0402; Part_type: RESISTORS\FIXED; Project: NEXTNAV_ORBIT_MODULE; RoHS: RoHS; Temperature: -55°C+155°C; Tolerance: 5%; Voltage: NA; Wattage: 1/16W; Weight: 0.65mg; Datasheet: Y:\MIS_DATABASE\DATASHEETS\RESISTORS\CRCW0603.PDF
R551 = RESISTOR: RES 2.2K 1/16W 5% 0402; Chkd/date: VASANTHA/061216; Crtd /date: BAVISH/021210; Custom_Duty: 15%; Customs_HS_Code: 85332119; Distributor_name: DIGIKEY; Distributor_part_number: 311-2.2KJRCT-ND; Footprint Path: Y:\MIS_DATABASE\Library\ALTIUM_TOOL\PCB_FOOTPRINTS\Altium_Footprint_Lib.PcbLib; Height: 0.40MM; Library Path: Y:\MIS_DATABASE\Library\ALTIUM_TOOL\SCHEMATICS_PARTS\MS_DISCRETE_Library.schlib; Mfr_name: YAGEO AMERICA; Mfr_part_number: RC0402JR-072K2L; Mistral Part No: 110010120018-R; Package: 0402; Part_type: RESISTORS\FIXED; Project: TE4; RoHS: RoHS; Temperature: -55°C+155°C; Tolerance: 5%; Voltage: NA; Wattage: 1/16W; Weight: 0.65mg; Datasheet: Y:\MIS_DATABASE\DATASHEETS\RESISTORS\RCXXXXL-SER_MAR18.PDF
R593 = RESISTOR: RES 12K 1/10W 1% 0402; Chkd/date: VASANTHA/041215; Crtd /date: VASANTHA/041215; Custom_Duty: 15%; Customs_HS_Code: 85332119; Distributor_name: DIGIKEY; Distributor_part_number: P12.0KLCT-ND; Footprint Path: Y:\MIS_DATABASE\Library\ALTIUM_TOOL\PCB_FOOTPRINTS\Altium_Footprint_Lib.PcbLib; Height: 0.40MM; Library Path: Y:\MIS_DATABASE\Library\ALTIUM_TOOL\SCHEMATICS_PARTS\MS_DISCRETE_Library.schlib; Mfr_name: PANASONIC-ECG; Mfr_part_number: ERJ-2RKF1202X; Mistral Part No: 110019040053-R; Package: 0402; Part_type: RESISTORS\FIXED; Project: TI_C5545; RoHS: RoHS; Temperature: -55°C+155°C; Tolerance: 1%; Voltage: NA; Wattage: 1/10W; Weight: 0.8mg; Datasheet: Y:\MIS_DATABASE\DATASHEETS\RESISTORS\PAN-ERJSER_NOV17.PDF
R612 = RESISTOR: RES 0E 1/8W 5% 0805; Chkd/date: VASANTHA/130416; Crtd /date: JEBRAN/020316; Custom_Duty: 15%; Customs_HS_Code: 85332119; Distributor_name: DIGIKEY; Distributor_part_number: 311-0.0ARCT-ND; Footprint Path: Y:\MIS_DATABASE\Library\ALTIUM_TOOL\PCB_FOOTPRINTS\Altium_Footprint_Lib.PcbLib; Height: 0.60MM; Library Path: Y:\MIS_DATABASE\Library\ALTIUM_TOOL\SCHEMATICS_PARTS\MS_DISCRETE_Library.schlib; Mfr_name: YAGEO AMERICA; Mfr_part_number: RC0805JR-070RL; Mistral Part No: 110009030074-R; Package: 0805; Part_type: RESISTORS\FIXED; Project: ZK_BIOMETRIC; RoHS: RoHS; Temperature: -55°C+155°C; Tolerance: 5%; Voltage: NA; Wattage: 1/8W; Weight: 5.5mg; Datasheet: Y:\MIS_DATABASE\DATASHEETS\RESISTORS\RCXXXXL-SER_MAR18.PDF
TP57 TP58 = TESTPOINT: TESTPOINT 0.56MM DRILL PTH; Chkd/date: BAVISH/040311; Crtd /date: MAZHAR/110405; Distributor_name: NA; Distributor_part_number: NA; Height: NA; Mfr_name: LOCAL; Mistral Part No: 130010010008; Package: THRU-HOLE; Project: KOPIN_MODULS; Temperature: NA; Tolerance: NA; Voltage: NA; Wattage: NA; Weight: NA; Datasheet: NA
TP60 TP61 = TESTPOINT: TESTPOINT CIR 20 SMD; Chkd/date: SHREESHAIL/171006; Crtd /date: MAZHAR/171006; Custom_Duty: NA; Customs_HS_Code: NA; Distributor_name: NA; Distributor_part_number: NA; Footprint Path: Y:\MIS_DATABASE\Library\ALTIUM_TOOL\PCB_FOOTPRINTS\Altium_Footprint_Lib.PcbLib; Height: NA; Library Path: Y:\MIS_DATABASE\Library\ALTIUM_TOOL\SCHEMATICS_PARTS\MS_DISCRETE_Library.schlib; MECHANICAL 3D STEP FILE: NA; Mfr_name: LOCAL; Mistral Part No: NA; Package: SMD; Project: BT MODULE_CSRBC04; RoHS: NA; Temperature: NA; Tolerance: NA; Voltage: NA; Wattage: NA; Weight: NA; Datasheet: NA
U44 = TPD2E001DRLR_SOT-5: IC ESD-PROTECTION DIODE ARRAYS SOT-5; Chkd/date: NAVEED/150714; Crtd /date: MUDDU/250510; Custom_Duty: 15%; Customs_HS_Code: 85423100; Distributor_name: DIGIKEY; Distributor_part_number: 296-21883-1-ND; Footprint Path: Y:\MIS_DATABASE\Library\ALTIUM_TOOL\PCB_FOOTPRINTS\Altium_Footprint_Lib.PcbLib; Height: 0.60MM; Library Path: Y:\MIS_DATABASE\Library\ALTIUM_TOOL\SCHEMATICS_PARTS\MS_FILTER_Library.schlib; Mfr_name: TEXAS INSTRUMENTS; Mistral Part No: 140110060007-R; Package: SOT-5; Part_type: ICS\ANALOG\ACTIVE FILTER; Project: CENTAURUS; RoHS: RoHS; Temperature: -40°C+85°C; Tolerance: NA; Voltage: NA; Wattage: NA; Weight: 2.8mg; Datasheet: Y:\MIS_DATABASE\DATASHEETS\ICS\MISC\TPD2E001DRLR.PDF
U46 = FT4232H_LQFP64: IC HIGH SPEED QUAD USB UART LQFP64; Chkd/date: MANIRAJA/110917; Crtd /date: VIJAYALAKSHMI/120813; Custom_Duty: 15%; Customs_HS_Code: 85423100; Distributor_name: DIGIKEY; Distributor_part_number: 768-1026-1-ND; Footprint Path: Y:\MIS_DATABASE\Library\ALTIUM_TOOL\PCB_FOOTPRINTS\Altium_Footprint_Lib.PcbLib; Height: 1.60MM; Library Path: Y:\MIS_DATABASE\Library\ALTIUM_TOOL\SCHEMATICS_PARTS\MS_COMBINATIONAL_Library.schlib; Mfr_name: FTDI; Mfr_part_number: FT4232HL-REEL; Mistral Part No: 141013080006-R; Package: LQFP64; Part_type: ICS\DIGITAL\PERIPHERAL; Project: DM37XX; RoHS: RoHS; Temperature: -40°C+85°C; Tolerance: NA; Voltage: NA; Wattage: NA; Weight: 342.7mg; Datasheet: Y:\MIS_DATABASE\DATASHEETS\ICS\DIGITAL\PERIPHERAL\FT4232HX.PDF
U87 = 93LC46B_MSOP8: IC 1K MICROWIRE COMPATIBLE SERIAL EEPROM MSOP8; Chkd/date: MANIRAJA/150218; Crtd /date: ALVY/150218; Custom_Duty: 15%; Customs_HS_Code: 85423100; Distributor_name: DIGIKEY; Distributor_part_number: 93LC46B-I/MS-ND; Footprint Path: Y:\MIS_DATABASE\Library\ALTIUM_TOOL\PCB_FOOTPRINTS\Altium_Footprint_Lib.PcbLib; Height: 1.10MM; Library Path: Y:\MIS_DATABASE\Library\ALTIUM_TOOL\SCHEMATICS_PARTS\MS_MISCMEMORY_Library.schlib; Mfr_name: MICROCHIP; Mfr_part_number: 93LC46B-I/MS; Mistral Part No: 141118020002-R; Package: MSOP8; Part_type: ICS\DIGITAL\MEMORY; Project: TI_MAXIE_CPB; RoHS: RoHS; Temperature: -40°C+85°C; Tolerance: NA; Voltage: NA; Wattage: NA; Weight: 140mg; Datasheet: Y:\MIS_DATABASE\DATASHEETS\ICS\MEMORY\93LC46B.PDF
U95 = TPS73501DRVR_SON6: IC 500mA LOW DROPOUT REGULATOR SON6; Chkd/date: VASANTHA/280915; Crtd /date: NAVEED/011014; Custom_Duty: 15%; Customs_HS_Code: 85423100; Distributor_name: DIGIKEY; Distributor_part_number: TPS73533DRVR-ND; Height: 0.80MM; Mfr_name: TEXAS INSTRUMENTS; Mistral Part No: 142014100001-R; Package: SON6; Part_type: ICS\POWER\VOLTAGE REGULATOR; Project: BLUETOOTH_WATCH; RoHS: RoHS; Temperature: -40°C+125°C; Tolerance: NA; Voltage: NA; Wattage: NA; Weight: NA; Datasheet: Y:\MIS_DATABASE\DATASHEETS\ICS\POWER\TPS735.PDF
Y3 = CRY4_13: CRY 12.000MHz 18pF SMD; Chkd/date: MANIRAJA/271021; Crtd /date: ALVY/271021; Custom_Duty: 24%; Customs_HS_Code: 85439000; Distributor_name: DIGIKEY; Distributor_part_number: XC2719CT-ND; Footprint Path: Y:\MIS_DATABASE\Library\ALTIUM_TOOL\PCB_FOOTPRINTS\Altium_Footprint_Lib.PcbLib; Height: 0.85MM; Library Path: Y:\MIS_DATABASE\Library\ALTIUM_TOOL\SCHEMATICS_PARTS\MS_DISCRETE_Library.schlib; Mfr_name: ECS INC; Mfr_part_number: ECS-120-18-30B-AGN-TR; Mistral Part No: 130021100037-R; Package: SMD; Part_type: CRYSTAL; Project: TI_AM62x SKEVM_BRD; RoHS: RoHS; Temperature: -40°C+85°C; Tolerance: NA; Voltage: NA; Wattage: NA; Weight: 159.425mg; Datasheet: Y:\MIS_DATABASE\DATASHEETS\MISC\CRY_OSC\ECS-53B.PDF
U12 = AM62-EVM_BGA425: IC AM62 SoC MICROPROCESSOR BGA425; Chkd/date: ALVY/110621; Crtd /date: MANIRAJA/110621; Custom_Duty: 15%; Customs_HS_Code: 85423100; Distributor_name: NA; Distributor_part_number: NA; Footprint Path: Y:\MIS_DATABASE\Library\ALTIUM_TOOL\PCB_FOOTPRINTS\Altium_Footprint_Lib.PcbLib; Height: 0.65MM; Library Path: Y:\MIS_DATABASE\Library\ALTIUM_TOOL\SCHEMATICS_PARTS\MS_MICROPROCESSOR_Library.schlib; Mfr_name: TEXAS INSTRUMENTS; Mistral Part No: 141221060001; Package: BGA425; Part_type: ICS\DIGITAL\MICROPROCESSOR; Project: AM62_EVM_BRD; RoHS: NA; Temperature: NA; Tolerance: NA; Voltage: NA; Wattage: NA; Weight: NA; Datasheet: Y:\MIS_DATABASE\DATASHEETS\ICS\DIGITAL\MICROCONTROLLER\AM62-SoC_SVB.PDF

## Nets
DGND: C174.2 C175.2 C177.1 C182.1 C183.1 C184.1 C187.1 C188.1 C437.1 C445.1 C450.1 C451.1 C452.1 C453.1 C456.1 C457.1 C458.1 C459.2 C460.1 C461.1 C462.1 C463.1 C464.1 C465.2 C466.1 C467.1 C471.1 C473.1 C475.1 C476.1 C478.1 C479.1 C480.1 C481.1 C482.2 C483.1 C484.2 C485.1 C487.1 C488.1 C489.1 C490.1 C492.1 C533.1 D7.1 J15.5(GND) J17.10 J17.12 J17.16 J17.20 R262.2 R526.1 R554.1 R558.1 R559.1 R562.1 R577.1 R593.1 R601.1 R608.1 R609.1 R612.1 U44.4(GND) U46.1(GND1) U46.5(GND2) U46.10(AGND) U46.11(GND3) U46.13(TEST) U46.15(GND4) U46.25(GND5) U46.35(GND6) U46.47(GND7) U46.51(GND8) U77.3(GND) U80.4(GND) U81.3(GND) U83.3(A2) U83.5(GND) U83.6(B2) U84.8(GND1) U84.9(GND2) U84.14(~{2OE}) U84.15(~{1OE}) U85.8(GND1) U85.9(GND2) U86.4(GND) U87.5(VSS) U88.8(GND1) U88.9(GND2) U91.3(GND) U92.8(GND1) U92.9(GND2) U92.14(~{2OE}) U92.15(~{1OE}) U93.5(1A2) U93.7(2A2) U93.8(GND1) U93.9(GND2) U93.10(2B2) U93.12(1B2) U93.14(~{2OE}) U93.15(~{1OE}) U95.3(GND) U95.7(EP) U96.3(A2) U96.5(GND) U96.6(B2) U97.8(GND1) U97.9(GND2) U97.14(~{2OE}) U97.15(~{1OE}) Y3.2 Y3.4 ; also on sheet 1 3 12 13 14 15 16 17 18 19 20 21 22 23 24 25 26 27 28 29 30 34 35 36 37 38 39 40 41 42 43 44 45
VCC3V3_XDS: C464.2 C466.2 C467.2 U83.8(VCCB) U85.16(VCCB) U86.8(VCCB) ; also on sheet 3 30
VCC_1V8_FT4232: C182.2 C183.2 C461.2 C465.1 U46.12(VCORE) U46.37(VCORE) U46.49(VREGOUT) U46.64(VCORE)
VCC_3V3_FT4232: C177.2 C187.2 C188.2 C453.2 C460.2 C476.2 C478.2 C482.1 C485.2 C488.2 FL25.2 FL26.2 LD13.2(ANODE) R541.2 R542.2 R543.2 U46.20(VCCIO) U46.31(VCCIO) U46.42(VCCIO) U46.50(VREGIN) U46.56(VCCIO) U84.16(VCCB) U87.8(VCC) U92.16(VCCB) U93.16(VCCB) U95.1(OUT) U97.16(VCCB)
VCC_3V3_SYS: C437.2 C445.2 C450.2 C451.2 C456.2 C457.2 C458.2 C462.2 C463.2 C473.2 C481.2 C484.1 C487.2 C489.2 C492.2 J17.5 R253.1 R254.1 R531.2 R537.2 R564.2 R574.2 R579.2 R592.1 R599.1 R602.2 R605.1 R606.2 R607.1 R611.1 R787.1 R788.1 U77.5(VCC) U80.1(VCCA) U80.8(VCCB) U81.5(VCC) U83.1(VCCA) U85.1(VCCA) U86.1(VCCA) U88.1(VCCA) U88.16(VCCB) U91.5(VCC) U93.1(VCCA) U96.1(VCCA) U96.8(VCCB) U97.1(VCCA) ; also on sheet 3 12 14 15 16 20 21 22 24 25 26 27 28 29 34 35 36 37 38 39 40 41 42 43 44 45
CAN_IO_3V3: C452.2 C475.2 R555.2 R561.1 R573.1 R578.2 R782.1 R783.1 U84.1(VCCA) U92.1(VCCA) ; also on sheet 1 17 36
FT4232_DO: R541.1 R551.2 U87.4(DO)
FT4232_EECLK: R542.1 U46.62(EECLK) U87.2(CLK)
FT4232_EECS: R543.1 U46.63(EECS) U87.1(CS)
FT4232_EEDATA: R551.1 U46.61(EEDATA) U87.3(DI)
FT4232_MCU_UART0_CTS_3V3: U46.53(DDBUS2) U84.10(2B2)
FT4232_MCU_UART0_RTS_3V3: U46.54(DDBUS3) U84.12(1B2)
FT4232_MCU_UART0_RX_3V3: U46.48(DDBUS0) U84.11(2B1)
FT4232_MCU_UART0_TX_3V3: U46.52(DDBUS1) U84.13(1B1)
FT4232_REF: R593.2 U46.6(REF)
FT4232_RESET: C184.2 R266.2 U46.14(~{RESET})
FT4232_SOC_UART0_RX_3V3: U46.16(ADBUS0) U93.11(2B1)
FT4232_SOC_UART0_TX_3V3: U46.17(ADBUS1) U93.13(1B1)
FT4232_SOC_UART1_CTS_3V3: U46.28(BDBUS2) U97.10(2B2)
FT4232_SOC_UART1_RTS_3V3: U46.29(BDBUS3) U97.12(1B2)
FT4232_SOC_UART1_RX_3V3: U46.26(BDBUS0) U97.11(2B1)
FT4232_SOC_UART1_TX_3V3: U46.27(BDBUS1) U97.13(1B1)
FT4232_USB_DM: J15.2(D-) U44.5(IO2) U46.7(DM)
FT4232_USB_DP: J15.3(D+) U44.3(IO1) U46.8(DP)
FT4232_USB_VBUS: C480.2 C483.2 C533.2 D7.2 J15.1(VBUS) U44.1(VCC) U95.4(EN) U95.6(IN)
FT4232_WKUP_UART0_CTS_3V3: U46.40(CDBUS2) U92.10(2B2)
FT4232_WKUP_UART0_RTS_3V3: U46.41(CDBUS3) U92.12(1B2)
FT4232_WKUP_UART0_RX_3V3: U46.38(CDBUS0) U92.11(2B1)
FT4232_WKUP_UART0_TX_3V3: U46.39(CDBUS1) U92.13(1B1)
FT_PWREN#: R257.1 U46.60(~{PWREN})
JTAG_cTI_RTCK: J17.9 R603.1
JTAG_cTI_TCK: J17.11 R537.1 R557.1 U81.1(B) U91.1(B)
JTAG_DIR: R559.2 U88.2(1DIR) U88.3(2DIR)
JTAG_EMU0: J17.13 R605.2 U80.7(B1)
JTAG_EMU1: J17.14 R607.2 U80.6(B2)
JTAG_EMU_RSTn: J17.15 R592.2 ; also on sheet 44
JTAG_TCK: R535.1 U88.12(1B2)
JTAG_TDI: J17.3 U88.10(2B2)
JTAG_TDIS: J17.4 R608.2
JTAG_TDO: J17.7 U96.7(B1)
JTAG_TMS: J17.1 U88.11(2B1)
JTAG_TRST#: J17.2 R562.2 U88.13(1B1)
MCU_UART0_CTS_3V3: U84.7(2A2) ; also on sheet 36
MCU_UART0_RTS_3V3: U84.5(1A2) ; also on sheet 36
MCU_UART0_RX_3V3: R783.2 U84.6(2A1) ; also on sheet 36
MCU_UART0_TX_3V3: R561.2 U84.4(1A1) ; also on sheet 36
SEL_XDS: U77.4(Y) U80.5(OE) U83.4(~{OE}) U85.14(~{2OE}) U85.15(~{1OE})
SEL_XDS110_INV: J17.8 R526.2 R531.1 U77.2(A) U81.2(A) U86.5(OE) U88.14(~{2OE}) U88.15(~{1OE}) U91.2(A) U96.4(~{OE})
SoC_EMU0: R254.2 U12.E12(EMU0) U80.2(A1) U86.2(A1)
SoC_EMU1: R253.2 U12.C11(EMU1) U80.3(A2) U86.3(A2)
SoC_TCK: R553.1 R565.1 R574.1 U12.A10(TCK)
SoC_TDI: R564.1 U12.A11(TDI) U85.4(1A1) U88.7(2A2)
SoC_TDO: R343.2 U83.2(A1) U96.2(A1)
SoC_TMS: R579.1 U12.B11(TMS) U85.6(2A1) U88.6(2A1)
SoC_TRST#: R262.1 U12.B10(TRSTN) U85.7(2A2) U88.4(1A1)
SOC_UART0_RX_3V3: R787.2 U93.6(2A1) ; also on sheet 44
SOC_UART0_TX_3V3: R599.2 U93.4(1A1) ; also on sheet 44
SOC_UART1_CTS: TP61.1(TP) U97.7(2A2) ; also on sheet 39
SOC_UART1_RTS: TP60.1(TP) U97.5(1A2) ; also on sheet 39
SOC_UART1_RXD: R788.2 TP57.1(TP) U97.6(2A1) ; also on sheet 39
SOC_UART1_TXD: R611.2 TP58.1(TP) U97.4(1A1) ; also on sheet 39
UART_SHIELD: J15.6(SH1) J15.7(SH2) J15.8(SH3) J15.9(SH4) R612.2
VPHY_3V3_FT4232: C471.2 FL25.1 U46.4(VPHY)
VPLL_3V3_FT4232: C479.2 FL26.1 R266.1 U46.9(VPLL)
WKUP_UART0_CTS_3V3: U92.7(2A2) ; also on sheet 34
WKUP_UART0_RTS_3V3: U92.5(1A2) ; also on sheet 34
WKUP_UART0_RX_3V3: R782.2 U92.6(2A1) ; also on sheet 34
WKUP_UART0_TX_3V3: R573.2 U92.4(1A1) ; also on sheet 34
XDS110_DIR: R554.2 U85.2(1DIR) U85.3(2DIR)
XDS110_EMU0: U86.7(B1) ; also on sheet 30
XDS110_EMU1: U86.6(B2) ; also on sheet 30
XDS110_TCK: U85.12(1B2) ; also on sheet 30
XDS110_TDI: U85.13(1B1) ; also on sheet 30
XDS110_TDO: U83.7(B1) ; also on sheet 30
XDS110_TMS: U85.11(2B1) ; also on sheet 30
XDS110_TRST#: U85.10(2B2) ; also on sheet 30
N16856152: C175.1 U46.3(OSCO) Y3.3
N16856224: C174.1 U46.2(OSCI) Y3.1
N16857368: C490.2 U95.2(NR/FB)
N16894003: R577.2 U92.3(2DIR)
N16894009: R578.1 U92.2(1DIR)
N16994873: R535.2 U81.4(Y)
N16994875: R603.2 U91.4(Y)
N16995245: C459.1 R557.2
N17030548: R343.1 U12.D12(TDO)
N17034231: R565.2 U88.5(1A2)
N17378539: LD13.1(CATHODE) R257.2
N18571509: R609.2 U97.3(2DIR)
N18571515: R606.1 U97.2(1DIR)
N20674580: R602.1 U93.2(1DIR)
N20674790: R601.2 U93.3(2DIR)
N20689650: R558.2 U84.3(2DIR)
N20689656: R555.1 U84.2(1DIR)
N20696645: R553.2 U85.5(1A2)

Not connected (* = marked no-connect by the designer): J15 4(ID)*; J17 17* 18* 19*; U44 2(NC)*; U46 18(ADBUS2)* 19(ADBUS3)* 21(ADBUS4)* 22(ADBUS5)* 23(ADBUS6)* 24(ADBUS7)* 30(BDBUS4)* 32(BDBUS5)* 33(BDBUS6)* 34(BDBUS7)* 36(~{SUSPEND})* 43(CDBUS4)* 44(CDBUS5)* 45(CDBUS6)* 46(CDBUS7)* 55(DDBUS4)* 57(DDBUS5)* 58(DDBUS6)* 59(DDBUS7)*; U77 1(NC)*; U87 6(NC1)* 7(NC2)*; U95 5(NC)*

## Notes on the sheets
sheet 31
- JTAG SOC SECTION
- cTI20 JTAG BUFFERS
- C
- BUFFER XDS110
- JTAG_DIR = H: A -> B
  JTAG_DIR = L: B -> A
  OE = H: output = Hi-Z
- XDS110_DIR = H: A -> B
  XDS110_DIR = L: B -> A
  OE = H: output = Hi-Z
- CAD Note:
  Buffers U88 and U96 need to be placed closer to the cTI - 20 pin connector J17
  to reduce the stub length of the JTAG signals.
sheet 32
- JTAG 20 PIN cTI CONNECTOR
- D-Note:
  TRSTn is the reset to the
  processor JTAG logic. For
  normal processor operation,
  this is pulled low, and thus
  the JTAG remains in reset
  as it is not being used.
  When an external JTAG pod
  is connected, the pod will
  eventually drive the TRSTn
  signal  high to release the
  JTAG logic from reset and
  enable a JTAG connection.
- Silk: cTI
- D-Note:
  Add provision for external ESD protection to provide system level ESD protection,
  when an external connector is used for debugging. Follow the Pin Connectivity
  Requirements table for connecting the required pulls for the SoC JTAG interface.
  Add test points and external ESD protection, when JTAG connector is not used.
- JTAG CLOCK BUFFER
- It should be connected to PORz of the SoC TBD
sheet 33
- FT4232 UART
- Silk: UART
- 90E
- DIR=H : A ->B
  DIR=L : B ->A
- D-Note:
  Follow SK-AM62P-LP for the latest
  FT4232 implementations.
- DIR=H : A ->B
  DIR=L : B ->A
- FT4232: 5V to 3.3V@500mA LDO
- ECS-120-18-30B-AGN-TR
- DIR=H : A ->B
  DIR=L : B ->A
- EEPROM
- R-Note:
  Verify the implementation with
  the device manufacturer.
- DIR=H : A ->B
  DIR=L : B ->A
